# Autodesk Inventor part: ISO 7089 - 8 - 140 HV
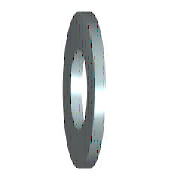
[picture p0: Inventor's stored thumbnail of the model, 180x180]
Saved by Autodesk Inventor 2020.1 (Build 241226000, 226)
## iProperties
Manager: www.cadconsulting.pl
Company: Fabian Stasiak CAD Consulting
Created: 2010-02
Part Number: ISO 7089 - 8 - 140 HV
Material: Spawana stal nierdzewna
Description: Podkładki okrągłe - Szereg normalny - Klasa dokładności A
Document SubType Name: Modeling
Standard: ISO 7089
Designer: F.Stasiak
Standard Revision: Second edition 2000-06-01
Standards Organization: ISO
Language: pl-PL
Size Designation: 8 - 140 HV
Categories: <MemberInstance><Categories><Category DisplayName="Mocowania" InternalName="e4da775c-781d-43d5-af7c-5136215cf5a6" Mnemonic="FSTN"><Category DisplayName="Podkład
Density: 8.08 g/cm^3
Appearance: Metal-Stal
IsCustomPart: 0
Author: F.Stasiak
Subject: Zbiór ćwiczeń. Autodesk Inventor 2020. Kurs podstawowy
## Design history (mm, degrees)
sketch "Sketch"
  geometry: C1 r 8 at (0, 0); C2 r 4.2 at (0, 0); 1 further point
  constraints: 2 centre point, 2 coincident
  dimensions: "d0" = 8.4 diameter of C2 (= SD1); "d1" = 16 diameter of C1 (= SD2)
extrude "Body" new body sketch "Sketch" distance "d2" = 1.6 (= SD); taper "d3" = 0 deg
workaxis "Work Axis1"
workplane "Work Plane1"
body "Solid1"
other parameters: "SD1" = 8.4 [user parameter; used in 1 equation term], "SD2" = 16 [user parameter; used in 1 equation term], "SD" = 1.6 [user parameter; used in 1 equation term], "d4" = 0, "d5" = 0, "d6" = 0, "d7" = 0, "NND" = 8 [user parameter]
